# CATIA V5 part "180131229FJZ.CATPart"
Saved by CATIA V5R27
Part number: Gear
Material "无"
Bounding box of the stored display mesh (mm): x -79.941 to 79.941, y -79.815 to 79.815, z -60 to 70
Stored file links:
  C:\Users\99747\Desktop\180131229FJZ.CATPart
  D:\齿轮步骤\DesignTable1.xls
  D:\CATIA2017\win_b64\startup\materials\Catalog.CATMaterial
  D:\CATIA2017\win_b64\startup\materials\scandinavian_fir.jpg
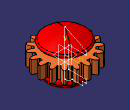
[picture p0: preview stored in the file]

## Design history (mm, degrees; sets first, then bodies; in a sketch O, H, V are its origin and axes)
Parameters
  `齿数z` = 18 {design table}
  `模数m` = 8 mm {design table}
  `压力角a` = 20 deg
  PI = 3.14159
  `分度圆半径r` = 72 mm {= `齿数z` *`模数m` *0.5}
  `齿顶圆半径rtop` = 80 mm {= `分度圆半径r` +`模数m`}
  `齿根圆半径rroot` = 62 mm {= `分度圆半径r` -1.25*`模数m`}
  `基圆半径rbase` = 67.6579 mm {= `分度圆半径r` *cos(`压力角a` )}
  `齿厚h` = 36 mm {= `分度圆半径r` *0.5}
  `减重槽半径r1` = 50.4 mm {= `分度圆半径r` *0.7}
  `减重槽深h1` = 7.2 mm {= `齿厚h` *0.2}
  `轮毂外径r2` = 57 mm {= int(`分度圆半径r` *0.8*1000)/1000}
  `轮毂长度h2` = 48 mm {= int(`轮毂外径r2`*0.85*1000)/1000}
  `小减重槽半径r` = 25 mm
  `键轴直径D` = 24 mm {= int(`齿根圆半径rroot` /2.5*1000)/1000}
  `键槽宽度W` = 5 mm {= int(`键轴直径D` /4.5*1000)/1000}
  `键槽深度T` = 1 mm {= int(`键槽宽度W` /3*1000)/1000}
  `工艺尺寸w` = 1 mm {= int(`齿厚h` /24*1000)/1000}
Body1 (main body)
  Circle1 "分度圆": type CtrRad, Start 0, End 180, Center {point type OnPlane, Support xy-plane, H 0, V 0, Direction (1, 0, 0)}, Support xy-plane, Radius 72 {= `分度圆半径r`}, FirstDirection (1, 0, 0)
  Circle2 "齿顶圆": type CtrRad, Start 0, End 180, Center {point type OnPlane, Support xy-plane, H 0, V 0, Direction (1, 0, 0)}, Support xy-plane, Radius 80 {= `齿顶圆半径rtop`}, FirstDirection (1, 0, 0)
  Circle3 "齿根圆": type CtrRad, Start 0, End 180, Center {point type OnPlane, Support xy-plane, H 0, V 0, Direction (1, 0, 0)}, Support xy-plane, Radius 62 {= `齿根圆半径rroot`}, FirstDirection (1, 0, 0)
  Circle4 "基圆": type CtrRad, Start 0, End 180, Center {point type OnPlane, Support xy-plane, H 0, V 0, Direction (1, 0, 0)}, Support xy-plane, Radius 67.6579 {= `基圆半径rbase`}, FirstDirection (1, 0, 0)
  Point1: type OnPlane, Support xy-plane, H 0, V 67.6579, Direction (1, 0, 0)
  Point2: type OnPlane, Support xy-plane, H 0.6924, V 70.9147, Direction (1, 0, 0)
  Point3: type OnPlane, Support xy-plane, H 2.3081, V 74.7582, Direction (1, 0, 0)
  Point4: type OnPlane, Support xy-plane, H 5.3764, V 79.7235, Direction (1, 0, 0)
  Point5: type OnPlane, Support xy-plane, H 10.2668, V 85.4158, Direction (1, 0, 0)
  Point6: type OnPlane, Support xy-plane, H 17.2556, V 91.3561, Direction (1, 0, 0)
  Point7: type OnPlane, Support xy-plane, H 26.5096, V 97.0013, Direction (1, 0, 0)
  Curve1: Elements (Point1; Point2; Point3; Point4; Point5; Point6; Point7)
  Extrapol1: ToExtrapol Point1, Support Curve1, Length 5.6579 {= (`基圆半径rbase` -`齿根圆半径rroot` )}
  Intersect1: ToIntersect1 Extrapol1, ToIntersect2 Circle1
  Line1: type PtPt, FirstPoint Intersect1, SecondPoint {point type OnPlane, Support xy-plane, H 0, V 0, Direction (1, 0, 0)}, Start 50
  Rotate1: ToTransfor Line1, Axis Z axis, Angle -5 {= -360deg/4/`齿数z`}
  Corner1: Element1 Circle3, Element2 Extrapol1, Radius 1 {= int((`基圆半径rbase` -`齿根圆半径rroot` )/4*1000)/1000}
  Symmetry1: ToTransfor Corner1, Reference Rotate1
  Trim1: Element1 Symmetry1, Element2 Corner1
  Trim2: Element1 Trim1, Element2 Circle2
  CircPattern1: of Trim2, instances 19 {= `齿数z` +1}, angular step 20 {= 360deg/`齿数z`}, axis from Z axis
  Split1: ToCut Circle3, Cutting CircPattern1
  Join1: Elements (CircPattern1; Split1)
  Pad1: profile Join1, length 18 {= `齿厚h` *0.5}, mirrored extent
  Sketch1 on xy-plane, origin (0, 0, 0), H (1, 0, 0), V (0, 1, 0)
    circle A1 centre (0, 0) radius 28.5
    radius A1 = 28.5 {= `轮毂外径r2` *0.5}
  Pad2: profile Sketch1, direction (0, 0, 1), length 24 {= `轮毂长度h2` *0.5}, mirrored extent
  Sketch2 on end face of Pad2, origin (0, 0, 24), H (1, 0, 0), V (0, 1, 0)
    line L1 (2.5, 13) -> (-2.5, 13)
    line L2 (-2.5, 13) -> (-2.5, 11.7367)
    line L3 (2.5, 11.7367) -> (2.5, 13)
    arc A1 centre (0, 0) radius 12 from (-2.5, 11.7367) to (2.5, 11.7367) ccw
    distance V L3 = 2.5 {= `键槽宽度W` *0.5}
    length L1 = 5 {= `键槽宽度W`}
    distance H L1 = 13 {= `键轴直径D` /2+`键槽深度T`}
    radius A1 = 12 {= `键轴直径D` /2}
    horizontal: L1 H
    vertical: L2 V, L3 V
  Pocket1: profile Sketch2, direction (0, 0, -1), through (limit type 3)
  Chamfer1: length 1 {= `工艺尺寸w`}, angle 45, on edge [start face of Pad2 | face of Pad2 from Sketch1.A1]; edge [face of Pad2 from Sketch1.A1 | end face of Pad2]
  Sketch3 on yz-plane, origin (0, 0, 0), H (0, 1, 0), V (0, 0, 1)
    point P1 (79, 18)
    line L1 (79, 18) -> (80, 18)
    point P2 (80, 18)
    line L2 (80, 18) -> (80, 17)
    point P3 (80, 17)
    line L3 (80, 17) -> (79, 18)
    point P4 (80, -18)
    point P5 (79, -18)
    line L4 (79, -18) -> (80, -18)
    point P6 (80, -17)
    line L5 (80, -18) -> (80, -17)
    line L6 (80, -17) -> (79, -18)
    angle L3 L1 = 45
    distance L1 H = 18 {= `齿厚h` *0.5}
    length L1 = 1 {= `工艺尺寸w`}
    distance L2 V = 80 {= `齿顶圆半径rtop`}
    horizontal: L1 H
    vertical: L2 V
    symmetry: P2 P4 H, P1 P5 H, L1 L4 H, P3 P6 H, L2 L5 H, L3 L6 H
  Groove1: profile Sketch3, axis Z axis, angle 360
Body2
  Sketch4 on yz-plane, origin (0, 0, 0), H (0, 1, 0), V (0, 0, 1)
    point P1 (0, 70)
    line L1 (0, 70) -> (60, 40)
    line L2 (60, 40) -> (60, 30)
    line L3 (60, 30) -> (10, 30)
    line L4 (10, 30) -> (10, -30)
    line L5 (10, -30) -> (60, -30)
    point P6 (60, -30)
    line L6 (60, -30) -> (60, -40)
    line L7 (60, -40) -> (50, -40)
    line L8 (50, -40) -> (50, -50)
    line L9 (50, -50) -> (20, -50)
    arc A1 centre (0, -35) radius 25 from (20, -50) to (0, -60) cw
    point P12 (0, -60)
    point P13 (0, -60)
    line L10 (0, 70) -> (0, -60)
    coincidence: P1 V, P6 L2, A1 P12, P12 V, V P13, P12 P13
    vertical: L2 V, L4 V, L6 V, L8 V, L10 V
    horizontal: L3 H, L5 H, L7 H, L9 H
  Shaft1: profile Sketch4, axis Sketch4.L10, angle 360
  Fillet1: radius 6, on edge [face of Shaft1 from Sketch4.L1 | face of Shaft1 from Sketch4.L2]; face of Shaft1 from Sketch4.L2; edge [face of Shaft1 from Sketch4.L5 | face of Shaft1 from Sketch4.L6]; edge [face of Shaft1 from Sketch4.L6 | face of Shaft1 from Sketch4.L7]; edge [face of Shaft1 from Sketch4.L8 | face of Shaft1 from Sketch4.L9]
  Point8: type OnPlane, Support face of Shaft1 from Sketch4.L9, H 0, V 0, Direction (1, 0, 0)
  Point9: type OnPlane, Support face of Shaft1 from Sketch4.L9, H -20, V -20, Direction (1, 0, 0)
  Point10: type OnPlane, Support face of Shaft1 from Sketch4.L9, H 20, V -20, Direction (1, 0, 0)
  Point11: type OnPlane, Support face of Shaft1 from Sketch4.L9, H -20, V 20, Direction (1, 0, 0)
  Point12: type OnPlane, Support face of Shaft1 from Sketch4.L9, H 20, V 20, Direction (1, 0, 0)
  Sketch5 on face of Shaft1 from Sketch4.L9, origin (20, 20, -50), H (1, 0, 0), V (0, -1, 0)
    point P1 (0, 0)
    reference projected point E1 (0, 0) from Point10
    coincidence: E1 P1
  Hole1: placed by Sketch5, at (20, 20, -50) direction (0, 0, 1), diameter 10, depth 20
  Sketch6 on face of Shaft1 from Sketch4.L9, origin (20, -20, -50), H (1, 0, 0), V (0, -1, 0)
    point P1 (0, 0)
    reference projected point E1 (0, 0) from Point12
    coincidence: E1 P1
  Hole2: placed by Sketch6, at (20, -20, -50) direction (0, 0, 1), diameter 10, depth 20
  Sketch7 on face of Shaft1 from Sketch4.L9, origin (-20, -20, -50), H (1, 0, 0), V (0, -1, 0)
    point P1 (0, 0)
    reference projected point E1 (0, 0) from Point11
    coincidence: E1 P1
  Hole3: placed by Sketch7, at (-20, -20, -50) direction (0, 0, 1), diameter 10, depth 20
  Sketch8 on face of Shaft1 from Sketch4.L9, origin (-20, 20, -50), H (1, 0, 0), V (0, -1, 0)
    point P1 (0, 0)
    reference projected point E1 (0, 0) from Point9
    coincidence: E1 P1
  Hole4: placed by Sketch8, at (-20, 20, -50) direction (0, 0, 1), diameter 10, depth 20
Relations
  design table, configuration 2, drives `齿数z`, `模数m`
